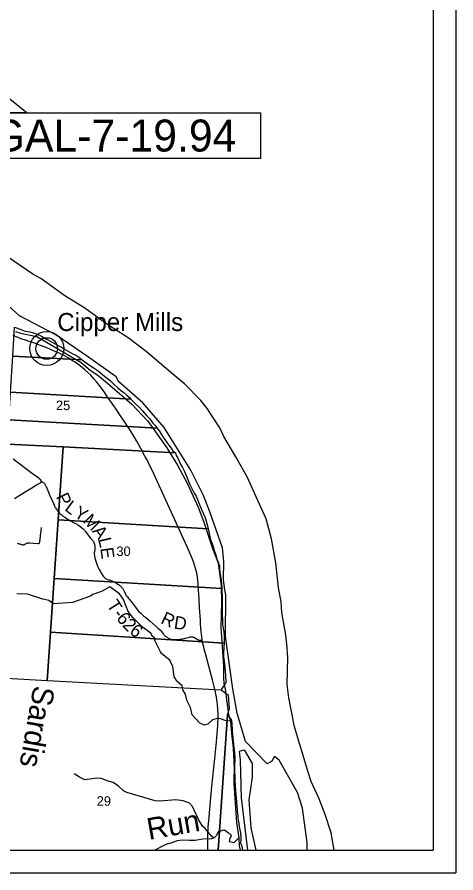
# Model space of a CAD drawing. Extents: x 0 to 34, y 0 to 22.
# Drawn here: x 7.078 to 9, y 14 to 17.749 of the extents above; entities that cross this region are included whole.
import ezdxf

# ---------------------------------------------------------------- set-up
doc = ezdxf.new("R2010")
doc.units = 0
for name, color, linetype in [('Default', 7, 'Continuous'), ('GM_X_County_Road', 7, 'Continuous'), ('GM_X_Major_River', 7, 'Continuous'), ('GM_X_Minor_River', 7, 'Continuous'), ('GM_X_Minor_River_Text', 7, 'Continuous'), ('GM_X_Section', 7, 'Continuous'), ('GM_X_Section_Text', 7, 'Continuous'), ('GM_X_State_Route', 7, 'Continuous'), ('GM_X_Township_Road', 7, 'Continuous'), ('GM_X_Township_Road_Text', 7, 'Continuous'), ('GM_X_Unincorporated', 7, 'Continuous'), ('GM_X_Unincorporated_Location', 7, 'Continuous'), ('GM_X_Unincorporated_Text', 7, 'Continuous'), ('SH_Data', 7, 'Continuous'), ('SH_Text', 7, 'Continuous')]:
    doc.layers.add(name, color=color, linetype=linetype)

msp = doc.modelspace()

# ---------------------------------------------------------------- linework, layer by layer
at = {"layer": 'Default'}
msp.add_lwpolyline([(4.8164, 14.1), (8.0885, 14.1), (8.061, 14.3293), (8.0568, 14.4942), (8.0527, 14.5333), (8.0727, 14.5386), (8.1075, 14.4794), (8.1079, 14.4192), (8.0935, 14.3206), (8.1018, 14.1967), (8.124, 14.1), (8.3491, 14.1), (8.3486, 14.1327), (8.3289, 14.2831), (8.307, 14.3525), (8.2254, 14.4931), (8.2061, 14.5102), (8.194, 14.4901), (8.1732, 14.4783), (8.0784, 14.5761), (8.0417, 14.7004), (8.0228, 14.8058), (7.9911, 15.0362), (7.9922, 15.2182), (7.9884, 15.2401), (7.9816, 15.2845), (7.9832, 15.3637), (7.9786, 15.4237), (7.9231, 15.5819), (7.894, 15.6537), (7.8399, 15.7649), (7.7224, 15.9516), (7.6283, 16.0594), (7.5243, 16.1516), (7.5119, 16.1725), (7.386, 16.2628), (7.2476, 16.3573), (7.0892, 16.4411), (6.9521, 16.5634)], dxfattribs=at)
for points in [[(6.9283, 14.1), (7.9595, 14.1), (8.0002, 14.6926), (8.0084, 14.7203), (8.0044, 14.7771), (8.0042, 14.7772), (7.9714, 14.8008), (7.21, 14.8415), (6.9776, 14.8549), (6.9622, 14.6076), (6.946, 14.3611), (6.9289, 14.1084)], [(7.9595, 14.1), (8.0672, 14.1), (8.0651, 14.1101), (8.0594, 14.1279), (8.0578, 14.1294), (8.0574, 14.1316), (8.0574, 14.1332), (8.0597, 14.1407), (8.0593, 14.1555), (8.0577, 14.1737), (8.053, 14.2029), (8.0488, 14.2256), (8.0468, 14.2373), (8.0461, 14.2483), (8.0453, 14.2585), (8.0421, 14.2903), (8.039, 14.3286), (8.0358, 14.3597), (8.0334, 14.4044), (8.0324, 14.465), (8.0327, 14.5025), (8.0322, 14.529), (8.0279, 14.5612), (8.026, 14.579), (8.0251, 14.5923), (8.0236, 14.6082), (8.0224, 14.6176), (8.0216, 14.6317), (8.02, 14.6491), (8.0204, 14.6563), (8.0188, 14.6638), (8.0181, 14.6676), (8.0161, 14.6741), (8.0002, 14.6926)]]:
    msp.add_lwpolyline(points, close=True, dxfattribs=at)
at = {"layer": 'GM_X_County_Road'}
msp.add_lwpolyline([(7.0667, 15.64), (7.0906, 15.6547), (7.1132, 15.6688), (7.1428, 15.6863), (7.1638, 15.6996), (7.1801, 15.7087), (7.1817, 15.7098), (7.1827, 15.7108), (7.1836, 15.712), (7.1842, 15.7133), (7.1844, 15.7148), (7.1844, 15.716), (7.1842, 15.7173), (7.1838, 15.7185), (7.1833, 15.7195), (7.1825, 15.7207), (7.1818, 15.7217), (7.1809, 15.7227), (7.1798, 15.7237), (7.1785, 15.7249), (7.1764, 15.7266), (7.1692, 15.7317), (7.1451, 15.7483), (7.1224, 15.7653), (7.0909, 15.7901), (7.0612, 15.8128)], dxfattribs=at)
at = {"layer": 'GM_X_Major_River'}
for points in [[(8.2115, 15.3578), (8.1918, 15.4639), (8.1684, 15.5504), (8.125, 15.6474), (8.0876, 15.7315), (8.0362, 15.8224), (7.9841, 15.9114), (7.9658, 15.9493), (7.9266, 16.0099), (7.9125, 16.033), (7.8825, 16.0689), (7.8115, 16.1419), (7.7599, 16.1842), (7.6442, 16.2847), (7.5707, 16.3394), (7.5597, 16.3474), (7.4706, 16.4036), (7.3743, 16.4746), (7.2879, 16.5274), (7.1822, 16.6044), (7.1477, 16.6232), (6.9976, 16.724)], [(7.0708, 16.372), (7.0939, 16.3645), (7.1654, 16.3492), (7.2848, 16.2802), (7.3594, 16.2357), (7.3989, 16.2025), (7.4326, 16.1806), (7.4747, 16.1451), (7.5805, 16.0536), (7.6489, 15.9799), (7.6591, 15.967), (7.7348, 15.8625), (7.7801, 15.7857), (7.8246, 15.7042), (7.8708, 15.6015), (7.8941, 15.5409), (7.9342, 15.4217), (7.9585, 15.359)], [(7.9585, 15.359), (7.9719, 15.2578), (7.973, 15.1853), (7.9699, 15.0756), (7.9767, 14.9918), (7.9821, 14.9058), (7.9817, 14.853), (7.9833, 14.831), (7.9895, 14.8049), (8.0041, 14.6942), (8.0133, 14.6651), (8.0174, 14.6112), (8.0253, 14.5471), (8.0292, 14.4554), (8.0275, 14.411), (8.0269, 14.3912), (8.0395, 14.2206), (8.0497, 14.1539), (8.0511, 14.1186), (8.0556, 14.1)], [(8.467, 14.1), (8.4531, 14.1757), (8.427, 14.2556), (8.4013, 14.3241), (8.3657, 14.4001), (8.3533, 14.4406), (8.2937, 14.6394), (8.268, 14.7664), (8.2609, 14.8255), (8.2636, 14.9443), (8.2595, 15.0019), (8.2555, 15.0409), (8.238, 15.1406), (8.2351, 15.1869), (8.2238, 15.2498), (8.2115, 15.3578)]]:
    msp.add_lwpolyline(points, dxfattribs=at)
at = {"layer": 'GM_X_Minor_River'}
for points in [[(8.0133, 14.6651), (7.99, 14.6677), (7.9698, 14.6751), (7.9544, 14.676), (7.9345, 14.6698), (7.9132, 14.6511), (7.8983, 14.6478), (7.8782, 14.6564), (7.8452, 14.692), (7.8375, 14.7249), (7.8219, 14.7566), (7.8159, 14.783), (7.8047, 14.8019), (7.8015, 14.8195), (7.7783, 14.8404), (7.7704, 14.8531), (7.7664, 14.8593), (7.7609, 14.9036), (7.7474, 14.9317), (7.7124, 14.9598), (7.7062, 14.968), (7.682, 15.0185), (7.6801, 15.0296), (7.6705, 15.0375), (7.6633, 15.0499), (7.6278, 15.076), (7.5857, 15.1188), (7.5653, 15.1449), (7.5446, 15.1979), (7.5265, 15.2232), (7.4846, 15.2526), (7.4481, 15.2333), (7.4397, 15.2298), (7.4103, 15.2189), (7.3991, 15.2117), (7.3208, 15.1846), (7.2378, 15.1781), (7.2175, 15.1936), (7.1908, 15.199), (7.1238, 15.2213), (7.0766, 15.2231)], [(7.9398, 14.1524), (7.9304, 14.1607), (7.9016, 14.195), (7.8898, 14.2042), (7.8736, 14.2313), (7.8471, 14.291), (7.8328, 14.3058), (7.8055, 14.3158), (7.7735, 14.3206), (7.7038, 14.3141), (7.6834, 14.3155), (7.559, 14.3522), (7.5445, 14.3591), (7.5228, 14.3799), (7.4987, 14.3966), (7.4729, 14.4032), (7.4553, 14.4109), (7.4471, 14.4131), (7.4278, 14.4145), (7.3751, 14.407), (7.352, 14.4199), (7.3283, 14.4343)], [(7.9639, 14.1822), (7.9608, 14.1811), (7.9506, 14.1617), (7.9419, 14.1534), (7.9291, 14.1491), (7.8924, 14.1479), (7.8588, 14.1418), (7.8316, 14.1421), (7.8017, 14.1428), (7.7798, 14.1397), (7.7427, 14.1274), (7.7393, 14.1285), (7.7212, 14.1205), (7.6812, 14.1)], [(7.963, 14.1819), (7.9748, 14.1857)], [(8.0048, 14.1737), (7.9861, 14.1873), (7.9804, 14.185), (7.9748, 14.1857)], [(8.0497, 14.1539), (8.0274, 14.1315), (8.0081, 14.1364), (8.0111, 14.1528), (8.0175, 14.1608), (8.0145, 14.1687), (8.0046, 14.1738)]]:
    msp.add_lwpolyline(points, dxfattribs=at)
at = {"layer": 'GM_X_Section'}
for points in [[(7.0589, 16.264), (7.0662, 16.3911), (7.0756, 16.3873), (7.0988, 16.3787), (7.1136, 16.3735), (7.134, 16.3697), (7.1496, 16.366), (7.1659, 16.3608), (7.1845, 16.351), (7.2046, 16.3401), (7.2316, 16.325), (7.2581, 16.3111), (7.2729, 16.3032), (7.2889, 16.2926), (7.32, 16.2757), (7.3352, 16.2685), (7.3439, 16.2625), (7.3565, 16.2534), (7.3629, 16.2482)], [(7.0589, 16.264), (7.3629, 16.2482), (7.3747, 16.2387), (7.3956, 16.224), (7.4153, 16.2108), (7.4328, 16.1988), (7.4545, 16.1814), (7.4742, 16.1659), (7.4875, 16.155), (7.5008, 16.1429), (7.5194, 16.1244), (7.5312, 16.115), (7.5453, 16.1048), (7.5586, 16.0935), (7.5704, 16.0825), (7.5767, 16.0755), (7.0498, 16.1061)], [(7.5767, 16.0755), (7.586, 16.0652), (7.6008, 16.0512), (7.6137, 16.0395), (7.6278, 16.0236), (7.6468, 16.0021), (7.6563, 15.9919), (7.6662, 15.9794), (7.6734, 15.9704), (7.6833, 15.9598), (7.6919, 15.9479), (7.0427, 15.9845), (7.0498, 16.1061)], [(7.0427, 15.9845), (7.6919, 15.9479), (7.7031, 15.9322), (7.7119, 15.9182), (7.7344, 15.885), (7.7427, 15.8732), (7.7526, 15.86), (7.7602, 15.8494), (7.772, 15.8408), (7.2798, 15.8662), (7.0366, 15.8787)], [(7.0366, 15.8787), (7.2798, 15.8662), (7.258, 15.5464), (7.2406, 15.29), (7.2246, 15.0549), (7.21, 14.8415), (6.9776, 14.8549), (6.9928, 15.1186), (7.0075, 15.3738), (7.0224, 15.6312)], [(7.2798, 15.8662), (7.772, 15.8408), (7.7755, 15.8283), (7.7804, 15.8196), (7.7884, 15.8041), (7.7957, 15.7878), (7.8029, 15.7753), (7.8121, 15.7579), (7.8209, 15.7386), (7.8262, 15.7235), (7.8335, 15.7049), (7.8438, 15.6841), (7.8545, 15.6637), (7.8621, 15.6497), (7.869, 15.6357), (7.8732, 15.6244), (7.8858, 15.5918), (7.8934, 15.5752), (7.9007, 15.5597), (7.9056, 15.5464), (7.9095, 15.5313), (7.9141, 15.515), (7.9156, 15.5072), (7.258, 15.5464)], [(7.9156, 15.5072), (7.9168, 15.5014), (7.9199, 15.4866), (7.9207, 15.4794), (7.9272, 15.4567), (7.9321, 15.4427), (7.9375, 15.428), (7.9417, 15.4117), (7.9486, 15.3931), (7.9509, 15.3799), (7.9645, 15.3449), (7.965, 15.3294), (7.9658, 15.3184), (7.9662, 15.315), (7.9696, 15.3002), (7.9727, 15.2824), (7.9747, 15.2495), (7.9749, 15.2458), (7.2406, 15.29), (7.258, 15.5464)], [(7.2406, 15.29), (7.9749, 15.2458), (7.9755, 15.2339), (7.9764, 15.212), (7.9757, 15.1968), (7.9757, 15.1896), (7.9761, 15.1832), (7.977, 15.1385), (7.9775, 15.1028), (7.9775, 15.0968), (7.9783, 15.0903), (7.9807, 15.0722), (7.9822, 15.0623), (7.983, 15.0593), (7.9846, 15.0339), (7.985, 15.0123), (7.9847, 15.0063), (7.2246, 15.0549)], [(7.9847, 15.0063), (7.984, 14.9903), (7.9826, 14.9627), (7.9826, 14.9464), (7.9846, 14.9267), (7.9877, 14.9017), (7.9885, 14.893), (7.9896, 14.8903), (7.9905, 14.8589), (7.9905, 14.8532), (7.9944, 14.8365), (7.9883, 14.8267), (7.9736, 14.8042), (7.9714, 14.8008), (7.21, 14.8415), (7.2246, 15.0549)]]:
    msp.add_lwpolyline(points, close=True, dxfattribs=at)
at = {"layer": 'GM_X_State_Route'}
for points in [[(7.1147, 16.3337), (7.1109, 16.3349), (7.0997, 16.3388), (7.0828, 16.3451), (7.0718, 16.3494), (7.0618, 16.3537)], [(7.9143, 14.1), (7.9139, 14.1136), (7.9139, 14.1192), (7.9138, 14.1247), (7.9138, 14.1341), (7.9137, 14.139), (7.9137, 14.145), (7.9137, 14.1489), (7.9138, 14.1558), (7.9138, 14.1601), (7.9138, 14.1632), (7.914, 14.1691), (7.9142, 14.1756), (7.9143, 14.18), (7.9144, 14.1819), (7.9145, 14.1843), (7.9146, 14.1868), (7.9148, 14.1918), (7.9151, 14.1967), (7.9154, 14.2016), (7.9155, 14.204), (7.9158, 14.207), (7.9162, 14.2112), (7.9164, 14.2142), (7.9169, 14.2198), (7.9175, 14.2259), (7.9205, 14.2631), (7.9254, 14.3125), (7.9273, 14.3317), (7.9317, 14.3781), (7.9436, 14.5013), (7.951, 14.5747), (7.9527, 14.5945), (7.9542, 14.6093), (7.9559, 14.6272), (7.9573, 14.6458), (7.9579, 14.6592), (7.9585, 14.6737), (7.9586, 14.6898), (7.9584, 14.7016), (7.9579, 14.7109), (7.9574, 14.7201), (7.9565, 14.7317), (7.9558, 14.7393), (7.9548, 14.7481), (7.9535, 14.7584), (7.9511, 14.7716), (7.9492, 14.7822), (7.947, 14.7925), (7.9446, 14.8034), (7.9414, 14.8163), (7.9383, 14.8287), (7.9339, 14.8454), (7.9238, 14.8833), (7.9042, 14.9553), (7.8979, 14.98), (7.8955, 14.9906), (7.8924, 15.0042), (7.8894, 15.0199), (7.8872, 15.0349), (7.8857, 15.0464), (7.8845, 15.0587), (7.8835, 15.0718), (7.8822, 15.0907), (7.8812, 15.107), (7.8776, 15.1633), (7.8753, 15.2011), (7.8717, 15.2594), (7.8708, 15.2701), (7.87, 15.2791), (7.8677, 15.297), (7.8648, 15.3135), (7.8615, 15.3286), (7.8572, 15.3441), (7.8525, 15.3589), (7.8466, 15.3745), (7.8383, 15.3946), (7.8232, 15.428), (7.6911, 15.7167), (7.6696, 15.7636), (7.6569, 15.7898), (7.6473, 15.8099), (7.6384, 15.8257), (7.6207, 15.8585), (7.6112, 15.8754), (7.6043, 15.8878), (7.5894, 15.9129), (7.573, 15.9392), (7.5476, 15.9783), (7.5289, 16.0061), (7.5117, 16.0311), (7.4912, 16.0609), (7.4748, 16.0846), (7.4604, 16.1053), (7.4469, 16.1247), (7.4352, 16.1407), (7.4264, 16.1518), (7.415, 16.1649), (7.4005, 16.1803), (7.3882, 16.1925), (7.3754, 16.2042), (7.3635, 16.2141), (7.3507, 16.2239), (7.3325, 16.2369), (7.3216, 16.244), (7.3019, 16.2558), (7.2808, 16.2676), (7.2648, 16.2758), (7.2484, 16.2833), (7.206, 16.301), (7.1771, 16.3122), (7.162, 16.318), (7.1562, 16.3201), (7.1492, 16.3226), (7.1393, 16.326), (7.131, 16.3287), (7.1147, 16.3337)]]:
    msp.add_lwpolyline(points, dxfattribs=at)
at = {"layer": 'GM_X_Township_Road'}
for points in [[(7.1842, 15.7133), (7.1865, 15.7129), (7.1886, 15.7125), (7.19, 15.712), (7.1914, 15.7114), (7.1929, 15.7105), (7.1943, 15.7094), (7.1957, 15.7081), (7.1969, 15.7067), (7.1982, 15.7052), (7.1994, 15.7034), (7.2008, 15.7012), (7.2019, 15.6992), (7.2032, 15.6969), (7.2042, 15.6948), (7.2052, 15.6927), (7.2127, 15.6753), (7.2206, 15.6568), (7.2385, 15.6151), (7.2404, 15.611), (7.2426, 15.6067), (7.2456, 15.6013), (7.2479, 15.5972), (7.2506, 15.5929), (7.2528, 15.5898), (7.2558, 15.586), (7.2591, 15.582), (7.2631, 15.5774), (7.2658, 15.5748), (7.2684, 15.5722), (7.2711, 15.5699), (7.2742, 15.5674), (7.2777, 15.5649), (7.2879, 15.5585), (7.3056, 15.5469), (7.3161, 15.5404), (7.3211, 15.5375), (7.3259, 15.5349), (7.3384, 15.5286), (7.3415, 15.5269), (7.345, 15.5248), (7.3484, 15.5225), (7.3511, 15.5205), (7.3536, 15.5185), (7.3658, 15.5085), (7.3684, 15.5062), (7.3709, 15.5037), (7.3732, 15.5013), (7.3756, 15.4985), (7.3782, 15.4951), (7.3987, 15.4676), (7.4039, 15.4622), (7.4059, 15.4603), (7.4079, 15.458), (7.41, 15.4556), (7.4113, 15.4537), (7.4128, 15.4513), (7.4139, 15.4491), (7.415, 15.4464), (7.4159, 15.4437), (7.4167, 15.4412), (7.4173, 15.4388), (7.4178, 15.4365), (7.4181, 15.4342), (7.4184, 15.4316), (7.4186, 15.4292), (7.4186, 15.4267), (7.4185, 15.424), (7.4183, 15.4206), (7.4166, 15.4056), (7.4164, 15.4033), (7.4163, 15.4007), (7.4164, 15.3983), (7.4165, 15.3962), (7.4166, 15.3939), (7.4169, 15.3912), (7.4172, 15.3885), (7.4177, 15.3859), (7.4182, 15.3832), (7.4192, 15.379), (7.4203, 15.375), (7.423, 15.3658), (7.429, 15.3481), (7.4318, 15.3413), (7.4349, 15.3344), (7.438, 15.3286), (7.4418, 15.3215), (7.4476, 15.3115), (7.4502, 15.3077), (7.4528, 15.304), (7.4558, 15.3002), (7.4593, 15.2959), (7.462, 15.2929), (7.4637, 15.2912), (7.4657, 15.2896), (7.4684, 15.2878), (7.4713, 15.2863), (7.4748, 15.2851), (7.4781, 15.2843), (7.4821, 15.2833), (7.486, 15.2822), (7.4905, 15.2808), (7.4956, 15.2787), (7.5023, 15.2754), (7.5087, 15.2718), (7.515, 15.2678), (7.5225, 15.2629), (7.5262, 15.2602), (7.5293, 15.2578), (7.5322, 15.2555), (7.5345, 15.2534), (7.5362, 15.2517), (7.5376, 15.2502), (7.5389, 15.2487), (7.5401, 15.2469), (7.5412, 15.245), (7.5425, 15.2429), (7.5439, 15.2403), (7.5455, 15.2373), (7.5469, 15.2344), (7.5528, 15.2216), (7.5547, 15.218), (7.5567, 15.2144), (7.5587, 15.2118), (7.5611, 15.209), (7.5666, 15.2028), (7.5683, 15.2005), (7.5701, 15.1982), (7.5821, 15.1824), (7.5955, 15.1657), (7.6107, 15.1471), (7.6201, 15.1373), (7.6227, 15.1346), (7.6257, 15.1317), (7.6286, 15.1292), (7.6324, 15.1261), (7.6409, 15.1196), (7.6527, 15.1095), (7.6606, 15.1025), (7.6867, 15.0789), (7.695, 15.0721), (7.7057, 15.0631), (7.7069, 15.0622), (7.7077, 15.0614), (7.7085, 15.0606), (7.7095, 15.0593), (7.7149, 15.0516), (7.7184, 15.0471), (7.7199, 15.0453), (7.7215, 15.0435), (7.7234, 15.0414), (7.7257, 15.0392), (7.7276, 15.0375), (7.7299, 15.0356), (7.7321, 15.0341), (7.7351, 15.032), (7.7381, 15.03), (7.7406, 15.0282), (7.743, 15.0267), (7.7451, 15.0255), (7.747, 15.0247), (7.7492, 15.024), (7.7515, 15.0235), (7.754, 15.0231), (7.7569, 15.0229), (7.7604, 15.0226), (7.7641, 15.0224), (7.7681, 15.0223), (7.7827, 15.0226), (7.7881, 15.0229), (7.793, 15.0234), (7.7974, 15.0241), (7.8017, 15.0248), (7.8061, 15.0257), (7.8108, 15.0268), (7.816, 15.0281), (7.8337, 15.0332), (7.8362, 15.0339), (7.8382, 15.0343), (7.84, 15.0346), (7.842, 15.0347), (7.8438, 15.0347), (7.8459, 15.0344), (7.848, 15.0339), (7.8496, 15.0334), (7.8511, 15.0328), (7.8526, 15.032), (7.8702, 15.0218), (7.872, 15.0209), (7.8738, 15.02), (7.8756, 15.0194), (7.8772, 15.0191), (7.8788, 15.0189), (7.8808, 15.0189), (7.883, 15.019), (7.8894, 15.0199)], [(7.0783, 15.4444), (7.0826, 15.4434), (7.087, 15.4423), (7.0903, 15.4413), (7.0932, 15.4403), (7.098, 15.4388), (7.1004, 15.4381), (7.1026, 15.4377), (7.1047, 15.4375), (7.1069, 15.4377), (7.1089, 15.4383), (7.1107, 15.439), (7.1127, 15.44), (7.1164, 15.4423), (7.1182, 15.4434), (7.1199, 15.4443), (7.1221, 15.4452), (7.1246, 15.4458), (7.127, 15.4461), (7.1298, 15.4461), (7.1333, 15.4459), (7.1493, 15.4445), (7.1693, 15.4427), (7.1707, 15.4427), (7.1721, 15.4427), (7.1732, 15.4429), (7.1742, 15.4433), (7.1751, 15.4439), (7.1759, 15.4448), (7.1765, 15.4459), (7.1769, 15.4469), (7.1772, 15.4482), (7.1778, 15.4505), (7.1784, 15.4543), (7.179, 15.4591), (7.181, 15.4775), (7.1834, 15.4973), (7.1836, 15.4995), (7.184, 15.502), (7.1856, 15.5128)]]:
    msp.add_lwpolyline(points, dxfattribs=at)
at = {"layer": 'GM_X_Unincorporated'}
for radius in [0.0744, 0.0472]:
    msp.add_circle((7.208, 16.2973), radius, dxfattribs=at)
at = {"layer": 'GM_X_Unincorporated_Location'}
msp.add_line((7.208, 16.2973), (7.208, 16.2973), dxfattribs=at)
at = {"layer": 'SH_Data'}
for p, q in [((9, 21), (9, 14)), ((8.9, 20.9), (8.9, 14.1)), ((2.1, 14.1), (8.9, 14.1)), ((2, 14), (9, 14))]:
    msp.add_line(p, q, dxfattribs=at)
at = {"layer": 'SH_Text'}
for points in [[(6.9128, 17.129), (6.4968, 17.8355), (7.122, 17.3299), (6.9128, 17.3299)], [(6.9128, 17.3299), (8.145, 17.3299), (8.145, 17.129), (6.9128, 17.129)]]:
    msp.add_lwpolyline(points, close=True, dxfattribs=at)
msp.add_lwpolyline([(2.1, 14.1), (8.0885, 14.1), (8.061, 14.3293), (8.0568, 14.4942), (8.0527, 14.5333), (8.0727, 14.5386), (8.1075, 14.4794), (8.1079, 14.4192), (8.0935, 14.3206), (8.1018, 14.1967), (8.124, 14.1), (8.3491, 14.1), (8.3486, 14.1327), (8.3289, 14.2831), (8.307, 14.3525), (8.2254, 14.4931), (8.2061, 14.5102), (8.194, 14.4901), (8.1732, 14.4783), (8.0784, 14.5761), (8.0417, 14.7004), (8.0228, 14.8058), (7.9911, 15.0362), (7.9922, 15.2182), (7.9884, 15.2401), (7.9816, 15.2845), (7.9832, 15.3637), (7.9786, 15.4237), (7.9231, 15.5819), (7.894, 15.6537), (7.8399, 15.7649), (7.7224, 15.9516), (7.6283, 16.0594), (7.5243, 16.1516), (7.5119, 16.1725), (7.386, 16.2628), (7.2476, 16.3573), (7.0892, 16.4411), (6.9521, 16.5634)], dxfattribs=at)

# ---------------------------------------------------------------- texts
at = {"layer": 'GM_X_Minor_River_Text'}
for s, height, rotation, p in [('Sardis', 0.0947, 259.9987, (7.151, 14.8245)), ('Run', 0.09469, 10.0015, (7.6555, 14.1444))]:
    msp.add_text(s, height=height, rotation=rotation, dxfattribs=at).set_placement(p)
at = {"layer": 'GM_X_Section_Text'}
for s, p in [('25', (7.2487, 16.0273)), ('30', (7.5133, 15.3881)), ('29', (7.4271, 14.294))]:
    msp.add_text(s, height=0.04186, rotation=0, dxfattribs=at).set_placement(p)
at = {"layer": 'GM_X_Township_Road_Text'}
for s, rotation, p in [('P', 295.7406, (7.2474, 15.6483)), ('L', 323.2377, (7.2828, 15.591)), ('Y', 330.0747, (7.323, 15.5615)), ('M', 314.386, (7.3631, 15.5391)), ('A', 307.4309, (7.405, 15.4964)), ('L', 283.3986, (7.4327, 15.4623)), ('E', 278.2483, (7.4423, 15.4223)), ('T', 302.5192, (7.4688, 15.1737)), ('-', 309.2461, (7.4959, 15.132)), ('6', 308.9817, (7.5106, 15.114)), ('2', 314.3218, (7.5365, 15.0825)), ('R', 334.8856, (7.7036, 15.0955)), ('D', 351.2587, (7.7625, 15.0706)), ('6', 321.8031, (7.567, 15.052))]:
    msp.add_text(s, height=0.0568, rotation=rotation, dxfattribs=at).set_placement(p)
at = {"layer": 'GM_X_Unincorporated_Text'}
msp.add_text('Cipper Mills', height=0.078977, rotation=0, dxfattribs=at).set_placement((7.2541, 16.3739))
at = {"layer": 'SH_Text'}
msp.add_text('GAL-7-19.94', height=0.14, dxfattribs=at).set_placement((6.9669, 17.1603))

doc.saveas('drawing.dxf')
